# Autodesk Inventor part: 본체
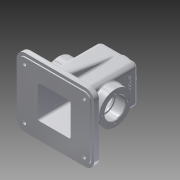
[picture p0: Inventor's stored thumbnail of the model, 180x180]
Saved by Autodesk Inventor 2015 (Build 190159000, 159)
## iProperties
Created: 2016-02
Part Number: 본체
Material: 알루미늄 6061
Document SubType Name: Modeling
Designer: Administrator
Density: 2.7 g/cm^3
Appearance: 알루미늄 - 평지
Mass: 855.756 g
Surface Area: 916.106 cm^2
Volume: 316.947 cm^3
Author: Administrator
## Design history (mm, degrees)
sketch "스케치1"
  geometry: L1 (65, 57.5)-(-65, 57.5); L2 (-65, 57.5)-(-65, -57.5); L3 (-65, -57.5)-(65, -57.5); L4 (65, -57.5)-(65, 57.5); L5 (65, 57.5)-(-65, -57.5); L6 (-65, 57.5)-(65, -57.5); 1 further point
  constraints: 12 end point, 2 midpoint, 2 parallel, 1 horizontal, 1 perpendicular
  dimensions: "d0" = 130 distance of L2.end L3.end; "d1" = 115 distance of L1.end L2.end
extrude "돌출1" new body sketch "스케치1" distance "d2" = 10; taper "d3" = 0 deg
sketch "스케치2"
  geometry: L1 (-60, -52.5)-(60, -52.5); L2 (60, -52.5)-(60, 52.5); L3 (60, 52.5)-(-60, 52.5); L4 (-60, 52.5)-(-60, -52.5); L5 (-60, -52.5)-(60, 52.5); L6 (60, -52.5)-(-60, 52.5); 1 further point
  constraints: 12 end point, 2 midpoint, 2 parallel, 1 horizontal, 1 perpendicular
  dimensions: "d4" = 120 distance of L2.end L3.end; "d5" = 105 distance of L1.end L2.end
extrude "돌출2" join sketch "스케치2" distance "d6" = 2; taper "d7" = 0 deg
node "작업 평면2"
sketch "스케치5"
  geometry: L1 (32.5, 32.5)-(-32.5, 32.5); L2 (-32.5, 32.5)-(-32.5, -32.5); L3 (-32.5, -32.5)-(32.5, -32.5); L4 (32.5, -32.5)-(32.5, 32.5); L5 (32.5, 32.5)-(-32.5, -32.5); L6 (-32.5, 32.5)-(32.5, -32.5); L7 (-65, -57.5)-(65, -57.5) reference; L8 (65, -57.5)-(65, 57.5) reference; L9 (65, 57.5)-(-65, 57.5) reference; L10 (-65, 57.5)-(-65, -57.5) reference; 1 further point
  constraints: 12 end point, 2 midpoint, 2 parallel, 1 horizontal, 1 perpendicular
  dimensions: "d12" = 25 distance between parallel lines of L7 L3; "d13" = 65 distance between parallel lines of L2 L4
extrude "돌출3" join sketch "스케치5" stored distance "d14" = 108; taper "d15" = 0 deg
node "작업 평면3"
sketch "스케치6"
  geometry: L1 (-2, -52.5)-(-2, 52.5) reference; C1 r 27.5 at (53, 0); 1 further point
  constraints: 1 centre point, 1 horizontal alignment
  dimensions: "d17" = 55 diameter of C1; "d18" = 55 distance from line of C1.centre L1
extrude "돌출4" join sketch "스케치6" stored distance "d19" = 95; taper "d20" = 0 deg
sketch "스케치7"
  geometry: L1 (-47.5, 25.5)-(-32.5, 25.5) reference; L2 (65, 10)-(-65, 10) reference; L3 (-42.5, 25.5)-(-42.5, 10); L4 (-32.5, 10)-(-32.5, 108) reference; 1 further point
  constraints: 2 end point, 2 point on line, 1 perpendicular
  dimensions: "d21" = 10 distance between parallel lines of L4 L3
feature "리브1" sketch "스케치7" dims "d22" = 1, "d23" = 6, "d24" = 0, "d25" = 0, "d26" = 1, "d27" = 1
node "작업 평면4"
sketch "스케치8"
  geometry: C1 r 20 at (0, 0); 1 further point
  constraints: 1 centre point, 1 coincident
  dimensions: "d29" = 40 diameter of C1
extrude "돌출5" join sketch "스케치8" distance "d30" = 10; taper "d31" = -5 deg
node "작업 평면5"
sketch "스케치9"
  geometry: L1 (125, 0)-(5, 0) reference; L2 (130, 10)-(0, 10) reference; L3 (60, 102)-(70, 102); L4 (70, 102)-(70, 10); L5 (70, 10)-(60, 10); L6 (60, 10)-(60, 102); L7 (60, 102)-(70, 10); L8 (70, 102)-(60, 10); 6 further points
  constraints: 12 end point, 6 midpoint, 2 parallel, 1 coincident, 1 horizontal, 1 perpendicular, 1 vertical alignment
  dimensions: "d33" = 10 distance of L3.start L3.end; "d34" = 92 distance between parallel lines of L2 L3
extrude "돌출6" join sketch "스케치9" stored distance "d35" = 10; taper "d36" = 0 deg
node "작업 평면6"
feature "면 기울기1" dims angle "d38" = 10 deg
node "작업 평면7"
node "작업 평면8"
sketch "스케치10"
  geometry: L1 (108, -32.5)-(108, 32.5) reference; L2 (108, 32.5)-(10, 32.5) reference; L3 (10, -32.5)-(108, -32.5) reference; L4 (-2, 27.5)-(103, 27.5); L5 (103, 27.5)-(103, -27.5); L6 (103, -27.5)-(-2, -27.5); L7 (-2, 52.5)-(-2, -52.5) reference; L8 (-2, 27.5)-(-2, -27.5); 1 further point
  constraints: 8 end point, 2 point on line, 2 other
  dimensions: "d41" = 5 distance between parallel lines of L1 L5
extrude "돌출7" cut sketch "스케치10" stored distance "d42" = 55; taper "d43" = 0 deg
node "작업 평면9"
sketch "스케치11"
  geometry: L1 (47.5, 25.5)-(47.5, 80.5) reference; L2 (-47.5, 80.5)-(-47.5, 25.5) reference; L3 (-60, -2)-(60, -2) reference; L4 (-47.5, 53)-(47.5, 53); L5 (-47.5, 53)-(-47.5, 70.5); L6 (-47.5, 70.5)-(-30.5, 70.5); L7 (-30.5, 70.5)-(-30.5, 68); L8 (-30.5, 68)-(30.5, 68); L9 (30.5, 68)-(30.5, 70.5); L10 (30.5, 70.5)-(47.5, 70.5); L11 (47.5, 53)-(47.5, 70.5); 1 further point
  constraints: 16 end point, 4 perpendicular, 2 horizontal, 2 midpoint, 2 point on line, 1 collinear
  dimensions: "d45" = 55 distance between parallel lines of L3 L4; "d46" = 35 diameter of L6 L4; "d47" = 35 diameter of L10 L4; "d48" = 30 diameter of L8 L4; "d49" = 17 distance between parallel lines of L7 L2; "d50" = 17 distance between parallel lines of L1 L9
revolve "회전1" sketch "스케치11" stored, may be unused: angle "d51" = 90 deg
sketch "스케치12"
  geometry: C1 r 17.5 at (0, 0) reference; 2 further points
  constraints: 1 vertical alignment
  dimensions: "d52" = 21 distance of C1.centre point (0, 21)
hole "구멍1" sketch "스케치12" at (0, 21) diameter "d53" = 3.242; stored, may be unused: countersink angle "d57" = 90 deg, drill point angle "d59" = 118 deg; dims "d54" = 8, "d55" = 4, "d56" = 2, "d58" = 10
node "작업 평면10"
node "작업 평면11"
sketch "스케치13"
  geometry: L1 (118, 19.125)-(118, -19.125) reference; C1 r 17.5 at (53, 0) reference; 2 further points
  constraints: 1 horizontal alignment, 1 other
  dimensions: "d65" = 26 distance from line of point (92, 0) L1
feature "엠보싱1" sketch "스케치13" dims "d66" = 0.5, "d67" = 0
sketch "스케치14"
  geometry: C1 r 10.5 at (0, 0); 1 further point
  constraints: 1 centre point, 1 coincident
  dimensions: "d68" = 21 diameter of C1
extrude "돌출8" cut sketch "스케치14" distance "d69" = 55; taper "d70" = 0 deg
sketch "스케치15"
  geometry: 2 further points
  constraints: 1 horizontal alignment
  dimensions: "d71" = 14.5 distance of point (14.5, 0) point (0, 0)
hole "구멍2" sketch "스케치15" at (14.5, 0) diameter "d72" = 2.459; stored, may be unused: countersink angle "d76" = 90 deg, drill point angle "d78" = 118 deg; dims "d73" = 7, "d74" = 4, "d75" = 2, "d77" = 9
sketch "스케치16"
  geometry: L1 (-65, 57.5)-(-65, -57.5) reference; L2 (65, 57.5)-(-65, 57.5) reference; L3 (65, -57.5)-(65, 57.5) reference; L4 (-65, -57.5)-(65, -57.5) reference; C1 r 7.5 at (-50, 42.5); C2 r 7.5 at (50, 42.5); C3 r 7.5 at (50, -42.5); C4 r 7.5 at (-50, -42.5); 1 further point
  constraints: 4 centre point, 3 equal radius
  dimensions: "d82" = 15 distance from line of L1 C1.centre; "d83" = 15 distance from line of L2 C1.centre; "d84" = 15 diameter of C1; "d85" = 15 distance from line of L2 C2.centre; "d86" = 15 distance from line of L3 C2.centre; "d87" = 15 distance from line of C3.centre L3; "d88" = 15 distance from line of C3.centre L4; "d89" = 15 distance from line of L1 C4.centre; "d90" = 15 distance from line of L4 C4.centre
extrude "돌출9" join sketch "스케치16" distance "d91" = 3; taper "d92" = 0 deg
hole "구멍3" diameter "d95" = 6; stored, may be unused: countersink angle "d99" = 90 deg, drill point angle "d101" = 118 deg; dims "d93" = 10, "d94" = 10, "d96" = 6, "d97" = 4, "d98" = 2, "d100" = 9
hole "구멍4" diameter "d104" = 6; stored, may be unused: countersink angle "d108" = 90 deg, drill point angle "d110" = 118 deg; dims "d102" = 10, "d103" = 10, "d105" = 6, "d106" = 4, "d107" = 2, "d109" = 9
hole "구멍5" diameter "d113" = 6; stored, may be unused: countersink angle "d117" = 90 deg, drill point angle "d119" = 118 deg; dims "d111" = 10, "d112" = 10, "d114" = 6, "d115" = 4, "d116" = 2, "d118" = 9
hole "구멍6" diameter "d122" = 6; stored, may be unused: countersink angle "d126" = 90 deg, drill point angle "d128" = 118 deg; dims "d120" = 10, "d121" = 10, "d123" = 6, "d124" = 4, "d125" = 2, "d127" = 9
fillet "모깎기1" dims "d129" = 15
fillet "모깎기2" dims "d130" = 3
fillet "모깎기3" dims "d131" = 3
fillet "모깎기4" dims "d132" = 10
fillet "모깎기5" dims "d133" = 8
fillet "모깎기6" dims "d134" = 8
chamfer "모따기1" distance "d135" = 1; stored, may be unused: second distance "d136" = 2, angle "d137" = 45 deg
fillet "모깎기8" dims "d139" = 0.3
fillet "모깎기9" dims "d140" = 3
fillet "모깎기10" dims "d141" = 3
fillet "모깎기11" dims "d142" = 3
fillet "모깎기12" dims "d143" = 3
fillet "모깎기13" dims "d144" = 3
fillet "모깎기14" dims "d145" = 1
fillet "모깎기15" dims "d146" = 3
fillet "모깎기16" dims "d147" = 3
node "솔리드1"
mirror "대칭1"
mirror "대칭2"
pattern_circular "원형 패턴1" dims angle "d61" = 360 deg
mirror "대칭3"
pattern_circular "원형 패턴2" dims angle "d80" = 360 deg
other parameters: "d11" = 54, "d16" = 0, "d28" = 0, "d37" = 0, "d39" = 0, "d40" = 0, "d44" = 0, "d63" = 0
